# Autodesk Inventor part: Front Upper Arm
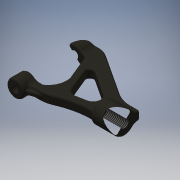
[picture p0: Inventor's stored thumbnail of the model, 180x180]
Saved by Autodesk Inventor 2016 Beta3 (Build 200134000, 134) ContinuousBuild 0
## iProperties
Shininess: 41.0
Compacted: True
Length Units: 11272
Angle Units: 11279
Time Units: 11290
Mass Units: 11286
Length Display Precision: 3
Angle Display Precision: 2
Company: Autodesk
Created: 2001-02
Part Number: Front Upper Arm
Document SubType Name: Modeling
Designer: Autodesk, Inc.
Material: Stiffzel
Project: Inventor Samples
Density: 1.28 g/cm^3
Mass: 3.32224 g
Surface Area: 21.7649 cm^2
Volume: 2.5955 cm^3
Appearance: Stiffzel
Density: 0.0
Volumn: 0.0
Area: 0.0
PropertySet Name: Model Information
Control State: 0
Master: False
Checked Out: False
Author: Autodesk, Inc.
Revision Number: A
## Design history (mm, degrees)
sketch "Sketch1"
  geometry: C1 r 3.81 at (-5.641, -1.052)
  constraints: 1 centre point
  dimensions: "d0" = 7.62 diameter of C1
extrude "Extrusion1" new body sketch "Sketch1" distance "d1" = 6.35; taper "d2" = 0 deg
workplane "Work Plane1"
sketch "Sketch2"
  geometry: C1 r 3.81 at (0, 0) reference
extrude "Extrusion2" join sketch "Sketch2" distance "d4" = 6.35; taper "d5" = 0 deg
workaxis "Work Axis2"
workplane "Work Plane4"
sketch "Sketch10"
  geometry: L1 (-3.81, 33.02)-(3.81, 33.02) reference; L2 (-3.81, 0)-(3.81, 0) reference; L3 (5.639, 22.012)-(-38.1, 22.012); L4 (0, -12.544)-(0, 73.201) reference; L5 (-3.81, 26.67)-(3.81, 26.67) reference; L6 (-3.81, 6.35)-(3.81, 6.35) reference; L7 (0, 26.67)-(-8.001, 26.67); L8 (-38.1, 27.722)-(-38.1, 27.722); L9 (-8.001, 30.099)-(0, 30.099); L10 (0, 30.099)-(0, 26.67); L11 (-38.1, 26.013)-(-27.305, 26.013); L12 (-27.305, 26.013)-(-27.305, 15.218); L13 (-33.972, 15.218)-(-38.1, 15.218); L14 (-38.1, 15.218)-(-38.1, 26.013); L15 (-3.81, 6.35)-(-4.793, 6.35); L16 (-3.81, 0)-(-4.793, 0); L17 (-8.818, 1.203)-(-27.005, 13.136); L18 (-30.178, 15.218)-(-27.305, 15.218); L19 (-8.818, 7.553)-(-23.424, 17.136); L20 (-3.81, 6.35)-(0, 6.35); L21 (0, 0)-(0, 6.35); L22 (-3.81, 0)-(0, 0); L23 (-3.81, 30.099)-(0, 30.099); L24 (0, 30.099)-(0, 26.67); L25 (-3.81, 26.67)-(0, 26.67); A1 r 34.94 centre (-27.305, 60.952) between (-27.305, 26.013) and (-13.147, 29.01); A2 r 38.369 centre (-27.305, 60.952) between (-22.112, 22.937) and (-11.758, 25.875); A3 r 12.7 centre (-8.001, 17.399) between (-8.001, 30.099) and (-13.147, 29.01); A4 r 9.271 centre (-8.001, 17.399) between (-8.001, 26.67) and (-11.758, 25.875); A5 r 7.338 centre (-4.793, 13.688) between (-8.818, 7.553) and (-4.793, 6.35); A6 r 7.338 centre (-4.793, 7.338) between (-8.818, 1.203) and (-4.793, 0); A7 r 3.175 centre (-21.682, 19.791) between (-22.112, 22.937) and (-23.424, 17.136); A8 r 12.7 centre (-33.972, 2.518) between (-27.005, 13.136) and (-33.972, 15.218); 2 further points
  constraints: 40 end point, 18 point on circle, 13 tangent, 10 point on line, 8 centre point, 8 parallel, 5 perpendicular, 3 collinear, 3 midpoint, 2 horizontal, 1 equal radius
  dimensions: "d41" = 22.01216 distance between parallel lines of L2 L3; "d42" = 38.1 distance from line of L4 L3.end; "d43" = 3.429 distance between parallel lines of L7 L9; "d44" = 10.795 distance of L11.end L12.end; "d45" = 4.0005 distance between parallel lines of L11 L3; "d46" = 3.429 radial gap between concentric circles of A2 A1; "d47" = 12.7 radius of A3; "d48" = 10.795 distance of L12.end L13.end; "d49" = 8.001 distance from line of L4 A3.centre; "d50" = 9.271 radius of A4 (= d47 - d46); "d53" = 3.175 distance of L2.start point (-6.985, 0); "d54" = 3.175 distance of L6.start point (-6.985, 6.35) (= d53); "d57" = 4.79257 distance from line of L4 A5.centre; "d58" = 3.175 radius of A7; "d62" = 12.7 radius of A8; "d63" = 4.1275 distance from line of A8.centre L14
extrude "Extrusion7" join sketch "Sketch10" stored distance "d59" = 4.1275; taper "d60" = 0 deg
sketch "Sketch11"
  geometry: L1 (4.793, -6.35)-(12.68, -25.48); L2 (15.665, -24.392)-(8.688, -7.47); A1 r 7.338 centre (4.793, -13.688) between (8.818, -7.553) and (4.793, -6.35) reference; A2 r 38.369 centre (27.305, -60.952) between (22.112, -22.937) and (11.758, -25.875) reference; A3 r 34.94 centre (27.305, -60.952) between (27.305, -26.013) and (13.147, -29.01) reference
  constraints: 4 end point, 3 point on circle, 1 parallel, 1 point on line
  dimensions: "d64" = 3.175 distance between parallel lines of L1 L2
extrude "Extrusion8" join sketch "Sketch11" distance "d65" = 4.1275; taper "d66" = 0 deg
workaxis "Work Axis4"
fillet "Fillet5" dims "d67" = 1.5875
fillet "Fillet6" dims "d68" = 3.175
sketch "Sketch13"
  geometry: L1 (8.818, 7.553)-(23.424, 17.136) reference; L2 (14.591, 21.786)-(8.688, 7.47) reference; A1 r 7.338 centre (4.793, 13.688) between (8.688, 7.47) and (8.818, 7.553) reference; A2 r 1.587 centre (12.114, 11.614) between (10.647, 12.219) and (12.985, 10.287)
  constraints: 2 point on circle, 2 point on line, 2 tangent, 1 centre point
  dimensions: "d69" = 1.5875 radius of A2
extrude "Extrusion9" join sketch "Sketch13" distance "d70" = 4.1275; taper "d71" = 0 deg
sketch "Sketch12"
  geometry: C1 r 4.763 at (4, 2.064); 1 further point
  constraints: 1 centre point, 1 coincident
  dimensions: "d72" = 9.525 diameter of C1
extrude "Extrusion10" join sketch "Sketch12" distance "d73" = 10.541; taper "d74" = 0 deg
fillet "Fillet7" dims "d75" = 3.175
fillet "Fillet8" dims "d76" = 0.8128
fillet "Fillet9" dims "d77" = 0.8128
fillet "Fillet10" dims "d78" = 0.8128
fillet "Fillet11" dims "d79" = 1.5875
fillet "Fillet12" dims "d80" = 0.8128
fillet "Fillet13" dims "d81" = 0.8128
fillet "Fillet14" dims "d82" = 0.8128
fillet "Fillet15" dims "d83" = 1.5875
fillet "Fillet16" dims "d84" = 0.8128
sketch "Sketch14"
  geometry: A1 r 3.95 centre (0, 0) between (2.967, 2.607) and (2.967, -2.607) reference
hole "Hole1" sketch "Sketch14" at (0, 0) diameter "d85" = 3.4036; stored, may be unused: countersink angle "d89" = 60 deg, drill point angle "d91" = 118 deg; dims "d86" = 12.7, "d87" = 9.525, "d88" = 6.35, "d90" = 9.525
sketch "Sketch15"
  geometry: C1 r 2.997 at (0, 0) reference
hole "Hole2" sketch "Sketch15" at (0, 0) diameter "d92" = 3.175; stored, may be unused: countersink angle "d96" = 60 deg, drill point angle "d98" = 118 deg; dims "d93" = 12.7, "d94" = 9.525, "d95" = 6.35, "d97" = 9.525
sketch "Sketch16"
  geometry: A1 r 8.262 centre (-0.572, 18.823) between (-4.209, 26.242) and (-8.592, 16.838)
  constraints: 2 point on circle, 1 centre point
feature "Rib1" sketch "Sketch16" dims "d99" = 2.54, "d100" = 1.5875
fillet "Fillet17" dims "d101" = 0.381
fillet "Fillet18" dims "d102" = 0.7874
sketch "Sketch17"
  geometry: L1 (-4.785, 31.833)-(-10.868, 29.523)
  constraints: 2 end point
feature "Rib2" sketch "Sketch17" dims "d103" = 2.54, "d104" = 1.5875
fillet "Fillet19" dims "d105" = 0.381
fillet "Fillet20" dims "d106" = 0.7874
body "Solid1"
other parameters: "d3" = 20.32, "d6" = 90 deg, "d12" = 90 deg, "d22" = 3.29029 (derived), "d35" = 90 deg, "d37" = 0, "d38" = 0
